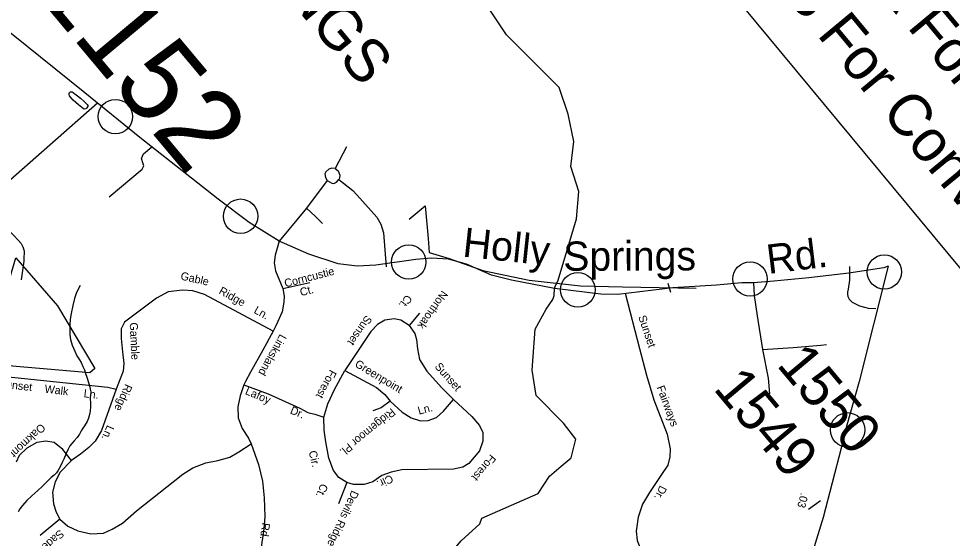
# Model space of a CAD drawing. Extents: x 2054826 to 2060231, y 685508 to 690809.
# Drawn here: x 2058702.3 to 2058951.1, y 689682.8 to 689821.4 of the extents above; entities that cross this region are included whole.
import ezdxf

# ---------------------------------------------------------------- set-up
doc = ezdxf.new("R2010")
doc.units = 0
for name, color, linetype in [('Default', 7, 'Continuous'), ('Old_Level_10', 7, 'Continuous'), ('Old_Level_11', 7, 'Continuous'), ('Old_Level_31', 7, 'Continuous'), ('Old_Level_32', 7, 'Continuous'), ('Old_Level_35', 7, 'Continuous'), ('Old_Level_48', 7, 'Continuous'), ('Old_Level_49', 7, 'Continuous'), ('Old_Level_50', 7, 'Continuous'), ('Old_Level_56', 7, 'Continuous'), ('Old_Level_59', 7, 'Continuous'), ('Old_Level_62', 7, 'Continuous'), ('Old_Level_8', 7, 'Continuous'), ('Prop Dimension Text', 7, 'Continuous'), ('Sheet Title CELL', 7, 'Continuous')]:
    doc.layers.add(name, color=color, linetype=linetype)

msp = doc.modelspace()

# ---------------------------------------------------------------- linework, layer by layer
at = {"layer": 'Default'}
msp.add_lwpolyline([(2058776.37, 689968.05), (2059134.67, 689535.97), (2058721.62, 689193.45), (2058363.32, 689625.52)], close=True, dxfattribs=at)
for centre in [(2058728.04, 689795.29), (2058761.4, 689768.72), (2058806.21, 689756.5), (2058932.96, 689753.85), (2058897.17, 689751.99), (2058851.28, 689749.09), (2058923.16, 689711.74)]:
    msp.add_circle(centre, 4.59, dxfattribs=at)
at = {"layer": 'Old_Level_10'}
msp.add_line((2058912.71, 689690.59), (2058915.94, 689692.93), dxfattribs=at)
at = {"layer": 'Old_Level_31'}
msp.add_line((2058845.09, 689749.43), (2058845.09, 689749.43), dxfattribs=at)
at = {"layer": 'Old_Level_32'}
for points in [[(2058898.06, 689750.93), (2058894.95, 689750.93), (2058888.19, 689750.36), (2058876.56, 689749.59), (2058861.91, 689747.84), (2058857.42, 689747.89), (2058845.09, 689749.43), (2058833.63, 689751.66), (2058828.28, 689753), (2058821.63, 689755.93), (2058816.8, 689757.3), (2058812.24, 689757.5), (2058808.13, 689757.14), (2058797.44, 689755.69), (2058792.44, 689755.38), (2058787.43, 689756.01), (2058779.61, 689758.56), (2058771.71, 689762.05), (2058763.67, 689767.02), (2058755.45, 689773.25), (2058734.54, 689789.73), (2058719.88, 689801.66), (2058700.32, 689817.33), (2058689.1, 689826.26)], [(2058933.99, 689755.37), (2058932.8, 689754.91), (2058923.51, 689753.56), (2058912.84, 689752.29), (2058903.53, 689751.43), (2058898.06, 689750.93)], [(2058933.99, 689755.37), (2058926.25, 689724.63), (2058922.75, 689712.41), (2058921.42, 689706.88), (2058916.65, 689688.35)], [(2058898.06, 689750.93), (2058898.31, 689747.59), (2058899.03, 689742.17), (2058900.45, 689733.2)], [(2058900.45, 689733.2), (2058908.62, 689733.75), (2058915.99, 689734.3), (2058917.55, 689734.53)], [(2058900.45, 689733.2), (2058901.98, 689725.52), (2058902.39, 689721.36)], [(2058916.65, 689688.35), (2058914.48, 689681.47), (2058911.85, 689671.65), (2058910.05, 689661.96), (2058907.79, 689655.31), (2058905.13, 689649.29), (2058897.33, 689631.9), (2058890.75, 689617.53), (2058885.69, 689606.14), (2058883.17, 689601.8), (2058877.58, 689593.44)]]:
    msp.add_lwpolyline(points, dxfattribs=at)
at = {"layer": 'Old_Level_35'}
for p, q in [((2058784.5, 689778.2), (2058778.97, 689770.85)), ((2058778.97, 689770.85), (2058771.71, 689762.05)), ((2058772.68, 689749.46), (2058779.86, 689751.04)), ((2058809.08, 689742.89), (2058806.3, 689739.55)), ((2058789.75, 689697.71), (2058787.48, 689692.01)), ((2058713.22, 689687.94), (2058707.95, 689683.54))]:
    msp.add_line(p, q, dxfattribs=at)
for points in [[(2058723.29, 689798.89), (2058697.86, 689776.5), (2058695.82, 689774.42), (2058695.59, 689773.35), (2058695.74, 689772.12), (2058695.73, 689771.61), (2058695.78, 689770.82), (2058695.96, 689770.29), (2058696.21, 689769.66), (2058696.51, 689768.98), (2058697.42, 689767.63), (2058698.67, 689765.97), (2058700.92, 689763.69), (2058702.24, 689762.25), (2058702.89, 689761.44), (2058703.39, 689760.51), (2058703.63, 689759.79), (2058703.72, 689759.27), (2058703.71, 689758.76), (2058703.66, 689757.89), (2058703.62, 689756.69), (2058702.94, 689751.73)], [(2058726.36, 689773.88), (2058735.17, 689781.25), (2058735.66, 689782.16), (2058735.44, 689782.73), (2058735.01, 689784.14), (2058735.53, 689785.33), (2058737.76, 689787.19)], [(2058789.63, 689787.23), (2058786.59, 689781.43), (2058787.42, 689780.79), (2058787.85, 689779.7), (2058787.78, 689778.87), (2058787.58, 689778.55)], [(2058786.59, 689781.43), (2058785.72, 689781.51), (2058784.89, 689781.26), (2058784.14, 689780.56), (2058783.89, 689779.98), (2058784.01, 689779.05), (2058784.5, 689778.2)], [(2058784.5, 689778.2), (2058785.72, 689777.53), (2058786.28, 689777.48), (2058786.95, 689777.82), (2058787.58, 689778.55)], [(2058787.58, 689778.55), (2058791.29, 689775.54), (2058792.4, 689774.4), (2058797.74, 689768.46), (2058798.74, 689766.64), (2058799.46, 689764.29), (2058800.17, 689755.22)], [(2058778.97, 689770.85), (2058781.35, 689768.63), (2058783.27, 689766.77)], [(2058771.71, 689762.05), (2058770.66, 689758.33), (2058770.35, 689756.3), (2058770.68, 689754.14), (2058772.68, 689749.46)], [(2058923.63, 689755.32), (2058923.67, 689752.73), (2058923.69, 689751.67), (2058923.34, 689749.3), (2058923.11, 689748.45), (2058923.1, 689747.94), (2058923.21, 689747.28), (2058923.56, 689746.64), (2058924.39, 689745.81), (2058926.32, 689744.86), (2058928.07, 689744.34), (2058928.66, 689744.23), (2058930.67, 689744.1)], [(2058770.08, 689738.09), (2058751.76, 689747.87), (2058748.65, 689748.78), (2058745.96, 689749.02), (2058742.08, 689748.57), (2058738.98, 689746.85), (2058730.49, 689740.48), (2058729.62, 689738.72), (2058729.62, 689736.09), (2058729.94, 689732.55), (2058730.31, 689729.48), (2058730.12, 689727.43), (2058728.26, 689722.61)], [(2058772.68, 689749.46), (2058773, 689747.4), (2058772.9, 689745.84), (2058772.46, 689743.19), (2058770.84, 689739.47), (2058770.08, 689738.09), (2058767.37, 689733.02), (2058764.03, 689727.13), (2058762.69, 689724.67), (2058762.24, 689723.79)], [(2058863.87, 689748.2), (2058867.67, 689733.44), (2058869.54, 689726.29), (2058871.57, 689719.78), (2058875.12, 689710.62), (2058875.88, 689706.65), (2058875.79, 689704.51), (2058875.22, 689702.33), (2058873.39, 689699.61), (2058870.38, 689695.04), (2058868.52, 689691.94), (2058867.37, 689688.42), (2058866.85, 689684.74), (2058867.09, 689682.2), (2058868.3, 689679.12), (2058871.21, 689675.23), (2058875.65, 689669.72), (2058877.47, 689667.14), (2058878.95, 689665.98), (2058881.72, 689665.73), (2058884.24, 689665.79), (2058885.25, 689665.61)], [(2058806.3, 689739.55), (2058804.15, 689740.97), (2058802.35, 689741.37), (2058799.85, 689741.03), (2058797.9, 689739.84), (2058796.14, 689737.93), (2058789.19, 689727.58)], [(2058806.3, 689739.55), (2058807.82, 689737.45), (2058808.32, 689735.81), (2058808.58, 689733.39), (2058809.12, 689730.47), (2058811.08, 689727.42), (2058814.91, 689723.01), (2058818.14, 689719.85)], [(2058683.23, 689727.61), (2058726, 689723.14), (2058728.26, 689722.61)], [(2058783.61, 689715.15), (2058784.64, 689718.65), (2058786.42, 689722.48), (2058789.19, 689727.58)], [(2058789.19, 689727.58), (2058797.65, 689723.08), (2058799.8, 689721.21), (2058801.31, 689719.4)], [(2058762.24, 689723.79), (2058761.33, 689720.83), (2058760.7, 689717.92), (2058760.78, 689714.98), (2058761.85, 689712.14), (2058763.49, 689709.5), (2058764.19, 689707.99)], [(2058762.24, 689723.79), (2058768.76, 689721.33), (2058777.2, 689717.55), (2058779.34, 689716.4), (2058781.21, 689715.92), (2058783.61, 689715.15)], [(2058728.26, 689722.61), (2058724.3, 689711.57), (2058722.69, 689708.76), (2058720.94, 689707), (2058718.71, 689705.28), (2058716.32, 689703.58)], [(2058818.14, 689719.85), (2058823, 689715.27), (2058825.11, 689712.93), (2058825.97, 689711.02), (2058826, 689708.7), (2058825.06, 689706.15), (2058822.2, 689702.74), (2058820.67, 689701.75), (2058818.16, 689701.26), (2058804.41, 689701.04), (2058801.49, 689700.5), (2058799.01, 689699.61), (2058796.63, 689697.9), (2058794.33, 689697.15), (2058791.53, 689697.16), (2058789.75, 689697.71)], [(2058801.31, 689719.4), (2058798.84, 689717.62), (2058796.61, 689716.79)], [(2058801.31, 689719.4), (2058804.48, 689716.49), (2058806.9, 689714.99), (2058809.38, 689714.14), (2058811.41, 689714.23), (2058813.64, 689715.07), (2058815.47, 689716.74), (2058818.14, 689719.85)], [(2058789.75, 689697.71), (2058787.63, 689699.02), (2058786.2, 689700.9), (2058784.9, 689704.21), (2058784.09, 689708.51), (2058783.65, 689711.66), (2058783.61, 689715.15)], [(2058716.32, 689703.58), (2058714.03, 689706.49), (2058711.72, 689708.37), (2058709.52, 689708.73), (2058707.14, 689708.35), (2058704.45, 689706.83), (2058702.37, 689704.94), (2058701.56, 689703.1)], [(2058713.22, 689687.94), (2058715.36, 689686.07), (2058718.04, 689684.8), (2058721.48, 689684.01), (2058724.85, 689684.19), (2058727.18, 689685.26), (2058729.96, 689686.85), (2058733.68, 689690.11), (2058745.97, 689699.96), (2058748.68, 689701.63), (2058752.18, 689702.95), (2058755.34, 689703.55), (2058758.54, 689704.46), (2058760.98, 689705.92), (2058764.19, 689707.99)], [(2058764.19, 689707.99), (2058766.14, 689702.54), (2058767.28, 689698.06), (2058767.69, 689693.65), (2058767.83, 689688.67), (2058767.56, 689685.33), (2058765.89, 689673.74), (2058765.28, 689667.56)], [(2058716.32, 689703.58), (2058713.3, 689700.46), (2058711.95, 689697.87), (2058711.31, 689695.13), (2058711.58, 689692), (2058712.26, 689689.78), (2058713.22, 689687.94)]]:
    msp.add_lwpolyline(points, dxfattribs=at)
at = {"layer": 'Old_Level_48'}
for points in [[(2058806.29, 689767.91), (2058810.56, 689771.49), (2058811.41, 689762.79), (2058811.69, 689759.01)], [(2058811.69, 689759.01), (2058816.99, 689757.4), (2058825.99, 689754.22), (2058838.29, 689751.63), (2058851.95, 689750.17), (2058863.21, 689749.92), (2058882.82, 689749.55)], [(2058701.55, 689757.6), (2058712.59, 689744.8), (2058722.56, 689728.12), (2058721.2, 689726.98), (2058691.22, 689729.57), (2058684.79, 689739.44), (2058691.41, 689744.98), (2058699.9, 689752.24), (2058701.55, 689757.6)]]:
    msp.add_lwpolyline(points, dxfattribs=at)
at = {"layer": 'Old_Level_49'}
for points in [[(2058806.29, 689767.91), (2058810.56, 689771.49), (2058811.41, 689762.79), (2058811.69, 689759.01)], [(2058811.69, 689759.01), (2058816.99, 689757.4), (2058825.99, 689754.22), (2058838.29, 689751.63), (2058851.95, 689750.17), (2058863.21, 689749.92), (2058882.82, 689749.55)], [(2058701.55, 689757.6), (2058712.59, 689744.8), (2058722.56, 689728.12), (2058721.2, 689726.98), (2058691.22, 689729.57), (2058684.79, 689739.44), (2058691.41, 689744.98), (2058699.9, 689752.24), (2058701.55, 689757.6)]]:
    msp.add_lwpolyline(points, dxfattribs=at)
at = {"layer": 'Old_Level_50'}
msp.add_line((2058845.09, 689749.43), (2058845.09, 689749.43), dxfattribs=at)
at = {"layer": 'Old_Level_56'}
msp.add_line((2058875.26, 689750.83), (2058875.99, 689748.49), dxfattribs=at)
at = {"layer": 'Old_Level_59'}
for points in [[(2058845.09, 689749.43), (2058845.24, 689749.98), (2058846.03, 689751.67), (2058850.9, 689768.02), (2058851.51, 689775.27), (2058849.4, 689781.98), (2058850.2, 689788.66), (2058848.74, 689795.92), (2058846.31, 689803.04), (2058832.29, 689817.11), (2058827.84, 689823.74)], [(2058846.82, 689702.02), (2058849.54, 689704.3), (2058850.77, 689709.24), (2058847.48, 689713.52), (2058840.21, 689720.87), (2058839.11, 689727.7), (2058839.91, 689738.62), (2058842.88, 689743.95), (2058844.63, 689746.49), (2058844.98, 689747.6), (2058845.09, 689749.43)], [(2058818.2, 689615.77), (2058812.79, 689622.18), (2058805.2, 689638.79), (2058801.04, 689643.8), (2058799.99, 689656.01), (2058801.37, 689658.56), (2058805.42, 689663.38), (2058805.32, 689664.36), (2058820.18, 689682.13), (2058825.15, 689686.66), (2058825.7, 689688.18), (2058840.68, 689694.74), (2058843.75, 689699.42), (2058846.82, 689702.02)]]:
    msp.add_lwpolyline(points, dxfattribs=at)
at = {"layer": 'Old_Level_62'}
for points in [[(2058719.73, 689799.32), (2058720.55, 689798.55), (2058720.71, 689798.26), (2058720.68, 689797.97), (2058720.36, 689797.55), (2058720.18, 689797.38), (2058719.74, 689797.29), (2058719.52, 689797.36), (2058718.23, 689798.38), (2058716.82, 689799.67), (2058716.18, 689800.41), (2058715.85, 689800.81), (2058715.75, 689801.22), (2058715.73, 689801.55), (2058715.84, 689801.72), (2058716.09, 689801.85), (2058716.5, 689801.85), (2058716.81, 689801.69), (2058717.24, 689801.38), (2058717.98, 689800.79), (2058718.75, 689800.17), (2058719.73, 689799.32)], [(2058718.68, 689750.24), (2058717.69, 689748.39), (2058717.18, 689746.77), (2058716.7, 689744.92), (2058716.24, 689742.75), (2058716.01, 689741.29), (2058715.93, 689739.77), (2058715.86, 689738.95), (2058715.88, 689738.11), (2058715.93, 689737.15), (2058716.09, 689735.83), (2058716.56, 689734.37), (2058717.21, 689732.7), (2058717.74, 689731.45), (2058718.44, 689730.42), (2058718.88, 689729.7), (2058719.39, 689728.67), (2058719.77, 689727.73), (2058720.1, 689726.73), (2058720.47, 689725.77), (2058720.98, 689724.15), (2058721.26, 689723.21), (2058721.35, 689722.6), (2058721.47, 689721.87), (2058721.45, 689720.98), (2058721.35, 689720.38), (2058721.33, 689719.79), (2058721.42, 689719.18), (2058721.45, 689717.93), (2058721.3, 689716.7), (2058721.13, 689715.8), (2058720.9, 689714.84), (2058720.54, 689713.95), (2058719.8, 689712.82), (2058719.34, 689712.17), (2058718.95, 689711.51), (2058718.51, 689710.62), (2058717.83, 689709.71), (2058717.02, 689708.86), (2058716.39, 689708.08), (2058715.92, 689707.44), (2058715.43, 689706.6), (2058714.88, 689705.46), (2058714.28, 689703.93), (2058713.88, 689703), (2058713.38, 689702.08), (2058713.05, 689701.46), (2058712.72, 689700.85), (2058712.38, 689700.32), (2058711.74, 689699.69), (2058710.9, 689699.07), (2058710.05, 689698.18), (2058708.52, 689696.65), (2058707.33, 689695.55), (2058705.78, 689694.16), (2058704.46, 689692.89), (2058703.29, 689691.56), (2058702.91, 689691.09), (2058702.61, 689690.66), (2058702.12, 689689.91)]]:
    msp.add_lwpolyline(points, dxfattribs=at)

# ---------------------------------------------------------------- texts
at = {"layer": 'Old_Level_10'}
for s, height, rotation, p in [('Gable', 2.133, 347.2341, (2058745.27, 689751.86)), ('Corncustie', 2.133, 14.6364, (2058773.37, 689749.73)), ('Ridge', 2.133, 331.0112, (2058755.42, 689748.18)), ('Ct.', 2.133, 14.6364, (2058777.52, 689747.37)), ('Northoak', 2.133, 235.1585, (2058815.07, 689749.06)), ('Ct.', 2.133, 231.2142, (2058805.66, 689747.97)), ('Ln.', 2.133, 331.0112, (2058764.75, 689743.03)), ('Sunset', 2.133, 235.1647, (2058794.85, 689742.46)), ('Sunset', 2.133, 288.5668, (2058867.35, 689741.9)), ('Gamble', 2.133, 272.608, (2058731.86, 689740.34)), ('Linksland', 2.133, 240.7015, (2058771.94, 689737.45)), ('Greenpoint', 2.133, 328.8209, (2058791.66, 689728.76)), ('Sunset', 2.133, 311.4267, (2058813, 689728.53)), ('Forest', 2.133, 241.6174, (2058785.24, 689727.97)), ('Sunset', 2.133, 353.3381, (2058696.92, 689723.09)), ('Walk', 2.133, 353.3381, (2058709.09, 689721.67)), ('Ridge', 2.133, 246.4453, (2058730.69, 689724.15)), ('Fairways', 2.133, 290.3498, (2058872.25, 689723.11)), ('Ln.', 2.133, 353.3381, (2058719.51, 689720.45)), ('Lafoy', 2.133, 336.7061, (2058762.44, 689721.35)), ('Dr.', 2.133, 336.7061, (2058774.42, 689716.2)), ('Ridgemoor Pl.', 2.1325, 219.1773, (2058801.58, 689717.66)), ('Ln.', 2.133, 15.139, (2058808.95, 689715.77)), ('Oakmont Ct.', 2.1325, 223.0852, (2058708.19, 689713.58)), ('Ln.', 2.133, 246.4453, (2058725.88, 689713.15)), ('Cir.', 2.133, 283.3395, (2058779.53, 689705.94)), ('Forest', 2.133, 229.6897, (2058828.04, 689705.38)), ('Cir.', 2.133, 205.8084, (2058801.43, 689699.89)), ('Ct.', 2.133, 245.414, (2058782.89, 689697.6)), ('Dr.', 2.133, 243.5121, (2058873.21, 689697.07)), ('Devils Ridge', 2.1325, 245.414, (2058791.07, 689695.76)), ('.03', 2.133, 255.4757, (2058910.73, 689695.1)), ('Rd.', 2.133, 262.0408, (2058767.17, 689687.06)), ('Sadelia Dr.', 2.1325, 221.3762, (2058713.21, 689685.27))]:
    msp.add_text(s, height=height, rotation=rotation, dxfattribs=at).set_placement(p)
at = {"layer": 'Old_Level_11'}
for s, rotation, p in [('Holly', 353.9309, (2058820.36, 689757.98)), ('Springs', 0.1878, (2058847.41, 689754.16)), ('Rd.', 7.0427, (2058902.06, 689753.31))]:
    msp.add_text(s, height=7.801, rotation=rotation, dxfattribs=at).set_placement(p)
at = {"layer": 'Old_Level_8'}
for s, height, p in [('1152', 21.964, (2058705.77, 689829.15)), ('1550', 10.796, (2058904.02, 689729.01)), ('1549', 10.796, (2058887.15, 689722.68))]:
    msp.add_text(s, height=height, rotation=309.9093, dxfattribs=at).set_placement(p)
at = {"layer": 'Prop Dimension Text'}
msp.add_text('HOLLY SPRINGS', height=11.4912, rotation=309.6672, dxfattribs=at).set_placement((2058714.84, 689898.13))
at = {"layer": 'Sheet Title CELL'}
for s, p in [('See Sheet 1-A For Index of Sheets', (2058873.72, 689897.69)), ('See Sheet 1-B For Conventional Symbols', (2058849.68, 689895.6))]:
    msp.add_text(s, height=11.25, rotation=309.6672, dxfattribs=at).set_placement(p)

doc.saveas('drawing.dxf')
